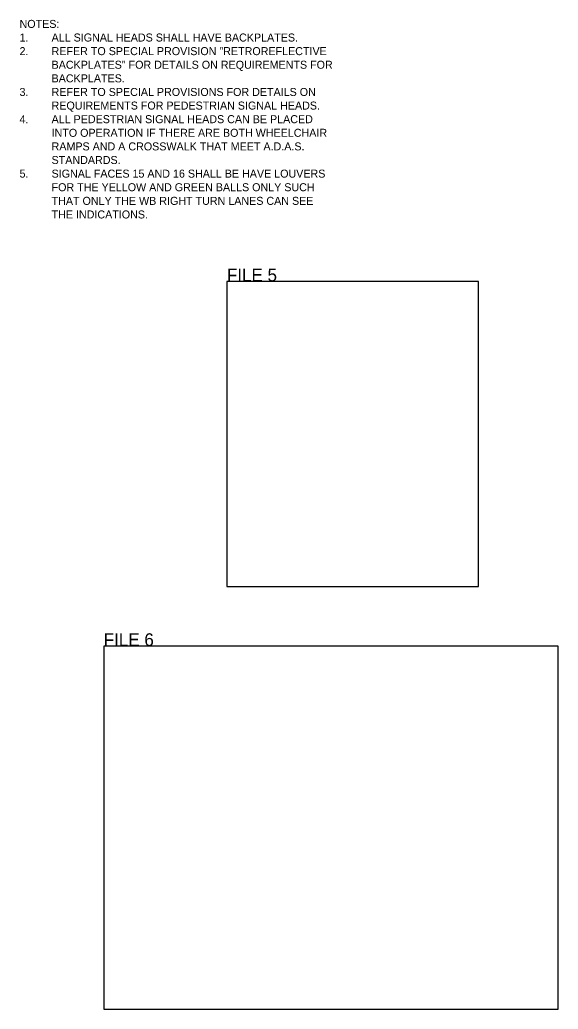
# Model space of a CAD drawing. Extents: x -218554 to 420030, y -565899 to -483460.
# Drawn here: x 418488 to 418771, y -565852 to -565333 of the extents above; entities that cross this region are included whole.
import ezdxf

# ---------------------------------------------------------------- set-up
doc = ezdxf.new("R2010")
doc.units = 0
doc.layers.add('G-ANNO-STMP', color=7, linetype='Continuous')
doc.layers.add('Template', color=7, linetype='Continuous')

msp = doc.modelspace()

# ---------------------------------------------------------------- linework, layer by layer
at = {"layer": 'Template'}
for points in [[(418728.86, -565470.29), (418596.87, -565470.29), (418596.87, -565630.35), (418728.86, -565630.35)], [(418770.61, -565661.57), (418532.27, -565661.57), (418532.27, -565852.09), (418770.61, -565852.09)]]:
    msp.add_lwpolyline(points, close=True, dxfattribs=at)

# ---------------------------------------------------------------- texts
at = {"layer": 'G-ANNO-STMP'}
for s, p in [('NOTES:', (418488.13, -565337.32)), ('1.', (418488.13, -565344.46)), ('ALL SIGNAL HEADS SHALL HAVE BACKPLATES.', (418504.93, -565344.46)), ('2.', (418488.13, -565351.6)), ('REFER TO SPECIAL PROVISION "RETROREFLECTIVE', (418504.93, -565351.6)), ('BACKPLATES" FOR DETAILS ON REQUIREMENTS FOR ', (418504.93, -565358.74)), ('BACKPLATES.', (418504.93, -565365.88)), ('3.', (418488.13, -565373.02)), ('REFER TO SPECIAL PROVISIONS FOR DETAILS ON', (418504.93, -565373.02)), ('REQUIREMENTS FOR PEDESTRIAN SIGNAL HEADS.', (418504.93, -565380.16)), ('4.', (418488.13, -565387.3)), ('ALL PEDESTRIAN SIGNAL HEADS CAN BE PLACED', (418504.93, -565387.3)), ('INTO OPERATION IF THERE ARE BOTH WHEELCHAIR', (418504.93, -565394.44)), ('RAMPS AND A CROSSWALK THAT MEET A.D.A.S.', (418504.93, -565401.58)), ('STANDARDS.', (418504.93, -565408.72)), ('5.', (418488.13, -565415.86)), ('SIGNAL FACES 15 AND 16 SHALL BE HAVE LOUVERS ', (418504.93, -565415.86)), ('FOR THE YELLOW AND GREEN BALLS ONLY SUCH ', (418504.93, -565423)), ('THAT ONLY THE WB RIGHT TURN LANES CAN SEE ', (418504.93, -565430.14)), ('THE INDICATIONS.', (418504.93, -565437.28))]:
    msp.add_text(s, height=4.2, dxfattribs=at).set_placement(p)
at = {"layer": 'Template'}
for s, p in [('FILE 5', (418596.87, -565470.29)), ('FILE 6', (418532.27, -565661.57))]:
    msp.add_text(s, height=6.667, rotation=360, dxfattribs=at).set_placement(p)

doc.saveas('drawing.dxf')
